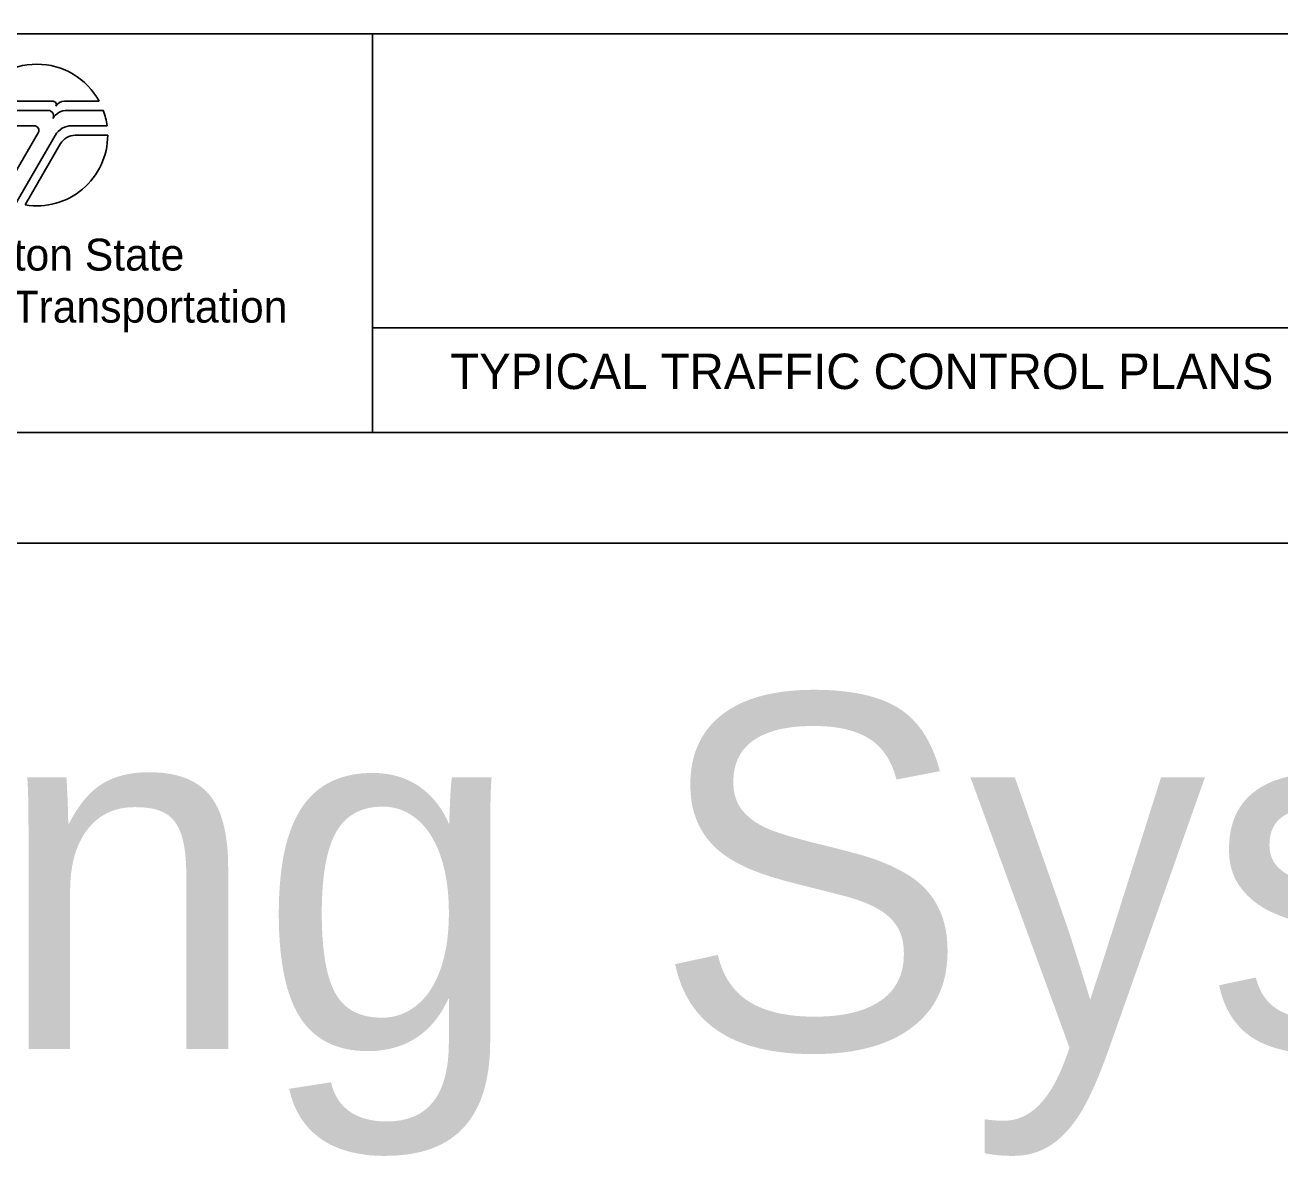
# Model space of a CAD drawing. Extents: x 99999 to 100116, y 99995 to 100013.
# Drawn here: x 100031.224 to 100034.769, y 99997.956 to 100001.15 of the extents above; entities that cross this region are included whole.
import ezdxf

# ---------------------------------------------------------------- set-up
doc = ezdxf.new("R2010")
doc.units = 0
for name, color, linetype in [('SH_GI_PlotLimits', 7, 'Continuous'), ('SH_GI_SheetBorder', 7, 'Continuous'), ('SH_GI_SheetLocationText', 7, 'Continuous'), ('SH_GI_SheetTextInCells', 7, 'Continuous'), ('SH_GI_TitleBlockText', 7, 'Continuous'), ('SH_GI_WSDOTLogo', 7, 'Continuous')]:
    doc.layers.add(name, color=color, linetype=linetype)

msp = doc.modelspace()

# ---------------------------------------------------------------- linework, layer by layer
at = {"layer": 'SH_GI_PlotLimits'}
msp.add_lwpolyline([(100019.0625, 99999.6875), (100036.0625, 99999.6875), (100036.0625, 100010.6875), (100019.0625, 100010.6875)], close=True, dxfattribs=at)
at = {"layer": 'SH_GI_SheetBorder'}
for p, q in [((100020, 100001.1259), (100035.75, 100001.1259)), ((100032.2055, 100001.1259), (100032.2055, 100000)), ((100032.2055, 100000.2955), (100035.2079, 100000.2955)), ((100020, 100000), (100035.75, 100000))]:
    msp.add_line(p, q, dxfattribs=at)
at = {"layer": 'SH_GI_WSDOTLogo'}
for p, q in [((100031.303, 100000.9354), (100031.0815, 100000.9354)), ((100031.433, 100000.9354), (100031.3351, 100000.9354)), ((100031.2894, 100000.9094), (100031.0697, 100000.9094)), ((100031.343, 100000.9094), (100031.3429, 100000.9094)), ((100031.4448, 100000.9094), (100031.343, 100000.9094)), ((100031.059, 100000.8661), (100031.2496, 100000.8661)), ((100031.3558, 100000.8661), (100031.4555, 100000.8661)), ((100031.261, 100000.8464), (100031.1567, 100000.6672)), ((100031.1989, 100000.6487), (100031.3089, 100000.839)), ((100031.2244, 100000.6428), (100031.3242, 100000.8156)), ((100031.3655, 100000.8394), (100031.4572, 100000.8394))]:
    msp.add_line(p, q, dxfattribs=at)
for centre, radius, start, end in [((100031.2572, 100000.84), 0.2, 28.4787, 151.532), ((100031.303, 100000.9263), 0.00903, 329.8742, 90.0033), ((100031.3352, 100000.9066), 0.0287, 90.0072, 148.1676), ((100031.2894, 100000.8946), 0.0148, 327.8418, 89.9985), ((100031.3429, 100000.861), 0.0484, 89.9953, 147.8238), ((100031.2572, 100000.84), 0.2, 7.4943, 20.2941), ((100031.2497, 100000.853), 0.0131, 329.7683, 90), ((100031.3558, 100000.8119), 0.0542, 90, 149.9974), ((100031.2572, 100000.84), 0.2, 260.5455, 359.8086), ((100031.3654, 100000.7918), 0.0476, 90, 150.0543)]:
    msp.add_arc(centre, radius, start, end, dxfattribs=at)

# ---------------------------------------------------------------- texts
at = {"layer": 'SH_GI_SheetLocationText'}
msp.add_text('3-Mile Queue Warning System', height=1, dxfattribs=at).set_placement((100019.2499, 99998.258))
at = {"layer": 'SH_GI_SheetTextInCells'}
for s, p in [('Washington State', (100030.7229, 100000.4571)), ('Department of Transportation', (100030.3916, 100000.3101))]:
    msp.add_text(s, height=0.090072, dxfattribs=at).set_placement(p)
at = {"layer": 'SH_GI_TitleBlockText'}
msp.add_text('TYPICAL TRAFFIC CONTROL PLANS', height=0.1, dxfattribs=at).set_placement((100032.4251, 100000.1224))

doc.saveas('drawing.dxf')
